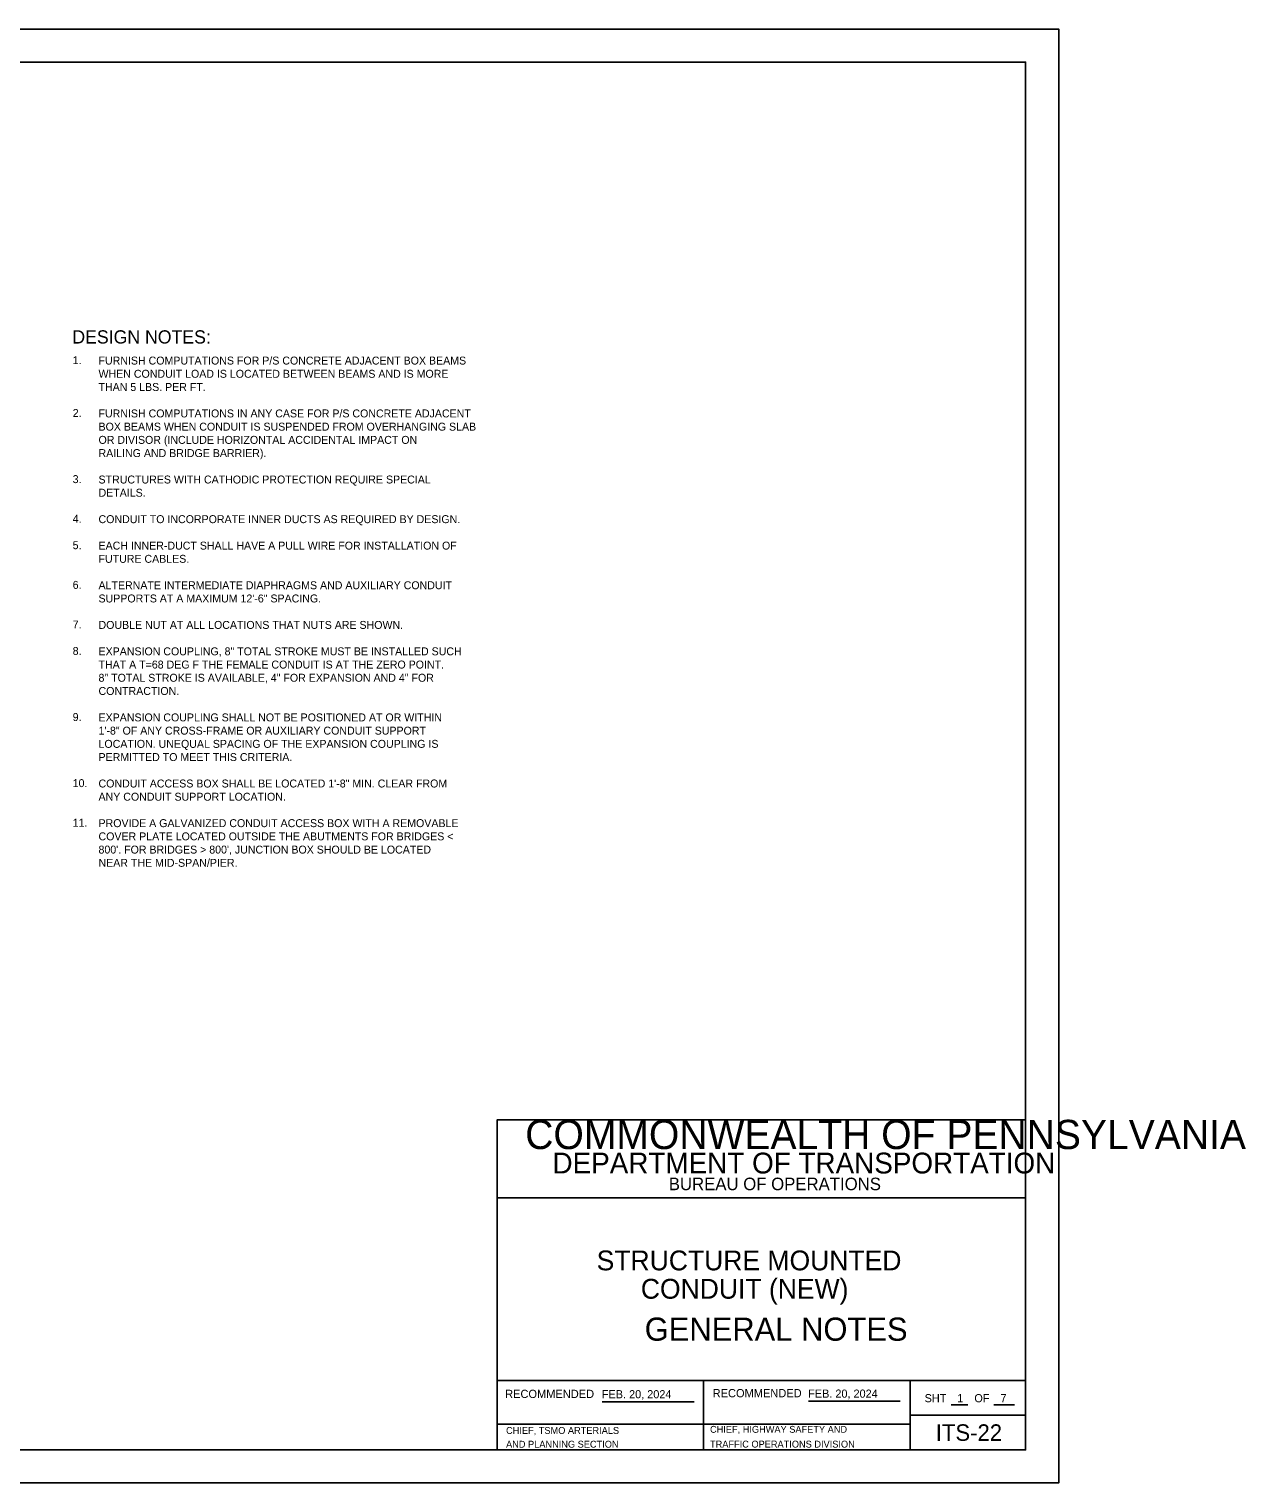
# Model space of a CAD drawing. Extents: x 1299104.8 to 1299141.6, y 239639.8 to 239661.8.
# Drawn here: x 1299123.22 to 1299141.64, y 239639.79 to 239661.79 of the extents above; entities that cross this region are included whole.
import ezdxf

# ---------------------------------------------------------------- set-up
doc = ezdxf.new("R2010")
doc.units = 0
for name, color, linetype in [('1', 7, 'Continuous'), ('2', 7, 'Continuous'), ('DIM TXT', 7, 'Continuous'), ('GS_noplot_1', 7, 'Continuous'), ('GS_plotshape_p', 7, 'Continuous'), ('Level 1', 7, 'Continuous'), ('PTEXT', 7, 'Continuous')]:
    doc.layers.add(name, color=color, linetype=linetype)

msp = doc.modelspace()

# ---------------------------------------------------------------- linework, layer by layer
at = {"layer": '1'}
for p, q in [((1299131.894, 239641.02), (1299133.284, 239641.02)), ((1299135.016, 239641.029), (1299136.405, 239641.029)), ((1299137.176, 239640.973), (1299137.427, 239640.973)), ((1299137.819, 239640.973), (1299138.133, 239640.973)), ((1299130.302, 239640.68), (1299133.427, 239640.68))]:
    msp.add_line(p, q, dxfattribs=at)
at = {"layer": 'GS_noplot_1'}
msp.add_lwpolyline([(1299130.302, 239641.339), (1299136.552, 239641.339), (1299136.552, 239640.291), (1299130.302, 239640.291)], close=True, dxfattribs=at)
at = {"layer": 'GS_plotshape_p'}
msp.add_lwpolyline([(1299104.802, 239661.791), (1299138.802, 239661.791), (1299138.802, 239639.791), (1299104.802, 239639.791)], close=True, dxfattribs=at)
at = {"layer": 'Level 1'}
for p, q in [((1299130.302, 239641.339), (1299138.302, 239641.339)), ((1299133.427, 239641.339), (1299133.427, 239640.291)), ((1299136.552, 239640.815), (1299138.302, 239640.815)), ((1299133.427, 239640.68), (1299136.552, 239640.68))]:
    msp.add_line(p, q, dxfattribs=at)
for points in [[(1299138.302, 239640.291), (1299106.302, 239640.291), (1299106.302, 239661.291), (1299138.302, 239661.291)], [(1299138.302, 239645.284), (1299130.302, 239645.284), (1299130.302, 239644.104), (1299138.302, 239644.104)], [(1299138.302, 239645.284), (1299130.302, 239645.284), (1299130.302, 239640.291), (1299138.302, 239640.291)]]:
    msp.add_lwpolyline(points, close=True, dxfattribs=at)

# ---------------------------------------------------------------- texts
at = {"layer": '1'}
for s, height, p in [('COMMONWEALTH OF PENNSYLVANIA', 0.44223, (1299130.728, 239644.843)), ('DEPARTMENT OF TRANSPORTATION', 0.31514, (1299131.141, 239644.474)), ('BUREAU OF OPERATIONS', 0.18955, (1299132.901, 239644.221)), ('RECOMMENDED', 0.125, (1299130.424, 239641.076)), ('FEB. 20, 2024', 0.12303, (1299131.889, 239641.072)), ('RECOMMENDED', 0.125, (1299133.565, 239641.087)), ('FEB. 20, 2024', 0.12303, (1299135.011, 239641.081)), ('CHIEF, TSMO ARTERIALS ', 0.10417, (1299130.438, 239640.533)), ('CHIEF, HIGHWAY SAFETY AND ', 0.10417, (1299133.525, 239640.55)), ('AND PLANNING SECTION', 0.10417, (1299130.438, 239640.325)), ('TRAFFIC OPERATIONS DIVISION', 0.10417, (1299133.525, 239640.326))]:
    msp.add_text(s, height=height, dxfattribs=at).set_placement(p)
at = {"layer": '2'}
for s, p in [('SHT', (1299136.773, 239641.012)), ('1', (1299137.267, 239641.013)), ('OF', (1299137.526, 239641.012)), ('7', (1299137.921, 239641.013))]:
    msp.add_text(s, height=0.123, dxfattribs=at).set_placement(p)
at = {"layer": 'DIM TXT'}
for s, height, p in [('DESIGN NOTES:', 0.2, (1299123.874, 239657.033)), ('1.', 0.12, (1299123.879, 239656.721)), ('FURNISH COMPUTATIONS FOR P/S CONCRETE ADJACENT BOX BEAMS ', 0.12, (1299124.27, 239656.715)), ('WHEN CONDUIT LOAD IS LOCATED BETWEEN BEAMS AND IS MORE ', 0.12, (1299124.27, 239656.515)), ('THAN 5 LBS. PER FT. ', 0.12, (1299124.27, 239656.315)), ('2.', 0.12, (1299123.879, 239655.921)), ('FURNISH COMPUTATIONS IN ANY CASE FOR P/S CONCRETE ADJACENT ', 0.12, (1299124.27, 239655.915)), ('BOX BEAMS WHEN CONDUIT IS SUSPENDED FROM OVERHANGING SLAB ', 0.12, (1299124.27, 239655.715)), ('OR DIVISOR (INCLUDE HORIZONTAL ACCIDENTAL IMPACT ON ', 0.12, (1299124.27, 239655.515)), ('RAILING AND BRIDGE BARRIER). ', 0.12, (1299124.27, 239655.315)), ('3.', 0.12, (1299123.879, 239654.921)), ('STRUCTURES WITH CATHODIC PROTECTION REQUIRE SPECIAL ', 0.12, (1299124.27, 239654.915)), ('DETAILS.', 0.12, (1299124.27, 239654.715)), ('4.', 0.12, (1299123.879, 239654.321)), ('CONDUIT TO INCORPORATE INNER DUCTS AS REQUIRED BY DESIGN.', 0.12, (1299124.27, 239654.315)), ('5.', 0.12, (1299123.879, 239653.921)), ('EACH INNER-DUCT SHALL HAVE A PULL WIRE FOR INSTALLATION OF ', 0.12, (1299124.27, 239653.915)), ('FUTURE CABLES. ', 0.12, (1299124.27, 239653.715)), ('6.', 0.12, (1299123.879, 239653.321)), ('ALTERNATE INTERMEDIATE DIAPHRAGMS AND AUXILIARY CONDUIT ', 0.12, (1299124.27, 239653.315)), ('SUPPORTS AT A MAXIMUM 12\'-6" SPACING.', 0.12, (1299124.27, 239653.115)), ('7.', 0.12, (1299123.879, 239652.721)), ('DOUBLE NUT AT ALL LOCATIONS THAT NUTS ARE SHOWN.', 0.12, (1299124.27, 239652.715)), ('8.', 0.12, (1299123.879, 239652.321)), ('EXPANSION COUPLING, 8" TOTAL STROKE MUST BE INSTALLED SUCH ', 0.12, (1299124.27, 239652.315)), ('THAT A T=68 DEG F THE FEMALE CONDUIT IS AT THE ZERO POINT.  ', 0.12, (1299124.27, 239652.115)), ('8" TOTAL STROKE IS AVAILABLE, 4" FOR EXPANSION AND 4" FOR ', 0.12, (1299124.27, 239651.915)), ('CONTRACTION.', 0.12, (1299124.27, 239651.715)), ('9.', 0.12, (1299123.879, 239651.321)), ('EXPANSION COUPLING SHALL NOT BE POSITIONED AT OR WITHIN ', 0.12, (1299124.27, 239651.315)), ('1\'-8" OF ANY CROSS-FRAME OR AUXILIARY CONDUIT SUPPORT ', 0.12, (1299124.27, 239651.115)), ('LOCATION. UNEQUAL SPACING OF THE EXPANSION COUPLING IS ', 0.12, (1299124.27, 239650.915)), ('PERMITTED TO MEET THIS CRITERIA. ', 0.12, (1299124.27, 239650.715)), ('10.', 0.12, (1299123.879, 239650.321)), ('CONDUIT ACCESS BOX SHALL BE LOCATED 1\'-8" MIN. CLEAR FROM ', 0.12, (1299124.27, 239650.315)), ('ANY CONDUIT SUPPORT LOCATION.', 0.12, (1299124.27, 239650.115)), ('11.', 0.12, (1299123.879, 239649.721)), ('PROVIDE A GALVANIZED CONDUIT ACCESS BOX WITH A REMOVABLE ', 0.12, (1299124.27, 239649.715)), ('COVER PLATE LOCATED OUTSIDE THE ABUTMENTS FOR BRIDGES < ', 0.12, (1299124.27, 239649.515)), ("800'. FOR BRIDGES > 800', JUNCTION BOX SHOULD BE LOCATED ", 0.12, (1299124.27, 239649.315)), ('NEAR THE MID-SPAN/PIER.', 0.12, (1299124.27, 239649.115)), ('ITS-22', 0.25, (1299136.942, 239640.428))]:
    msp.add_text(s, height=height, dxfattribs=at).set_placement(p)
at = {"layer": 'PTEXT'}
for s, height, p in [('STRUCTURE MOUNTED', 0.3, (1299131.809, 239643.008)), ('CONDUIT (NEW)', 0.3, (1299132.478, 239642.579)), ('GENERAL NOTES', 0.35, (1299132.536, 239641.943))]:
    msp.add_text(s, height=height, dxfattribs=at).set_placement(p)

doc.saveas('drawing.dxf')
